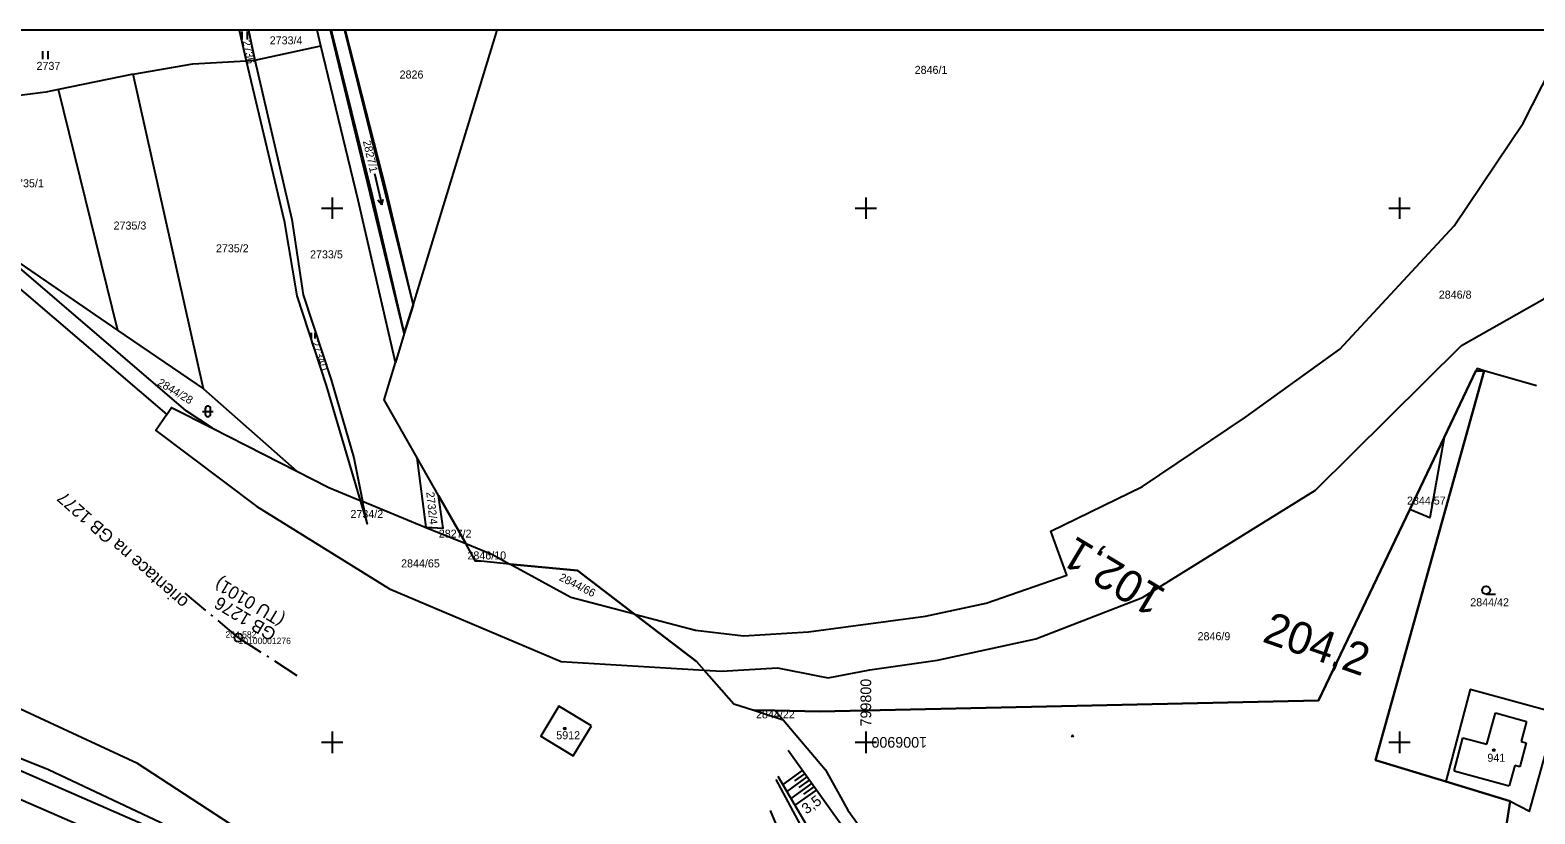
# Model space of a CAD drawing. Extents: x -800194 to -799078, y -1007177 to -1006597.
# Drawn here: x -799956.6 to -799674.6, y -1006913.4 to -1006766.6 of the extents above; entities that cross this region are included whole.
import ezdxf

# ---------------------------------------------------------------- set-up
doc = ezdxf.new("R2010")
doc.units = 0
for name, color, linetype in [('_Vrstva 7 - Přesunutá', 7, 'Continuous'), ('Dočasné zábory', 7, 'Continuous'), ('Legenda 1', 7, 'Continuous'), ('Ramove udaje', 7, 'Continuous'), ('Vrstva 48', 7, 'Continuous'), ('Vrstva 49', 7, 'Continuous'), ('Vrstva 53', 7, 'Continuous'), ('Vrstva 55', 7, 'Continuous'), ('Vrstva 56', 7, 'Continuous'), ('Vrstva 57', 7, 'Continuous'), ('Vrstva 58', 7, 'Continuous'), ('Vrstva 59', 7, 'Continuous'), ('Vrstva 60', 7, 'Continuous'), ('Vrstva 61', 7, 'Continuous'), ('Vrstva 63', 7, 'Continuous'), ('Vrstva 7', 7, 'Continuous')]:
    doc.layers.add(name, color=color, linetype=linetype)

msp = doc.modelspace()

# ---------------------------------------------------------------- linework, layer by layer
at = {"layer": 'Dočasné zábory'}
for points in [[(-799967.93, -1006901.13), (-799932.44, -1006916.61), (-799908.96, -1006929.95), (-799851.52, -1006962.6), (-799849.43, -1006965.58), (-799838.48, -1006981.29), (-799834.59, -1006980.15), (-799830.67, -1006986.18), (-799829.24, -1006997.61), (-799828.14, -1006999.18)], [(-799827.49, -1007007.33), (-799833.05, -1007000.26), (-799836.6, -1006993.51), (-799842.29, -1006982.66), (-799845.94, -1006977.53), (-799850.11, -1006971.65), (-799853.92, -1006967.55), (-799855.04, -1006966.34), (-799901.91, -1006939.71), (-799934.68, -1006921.09), (-799969.58, -1006905.87)]]:
    msp.add_lwpolyline(points, dxfattribs=at)
at = {"layer": 'Legenda 1'}
msp.add_lwpolyline([(-800193.4, -1007176.65), (-799312.4, -1007176.65), (-799312.4, -1006766.65), (-800193.4, -1006766.65)], close=True, dxfattribs=at)
at = {"layer": 'Ramove udaje'}
for p, q in [((-799900, -1006798), (-799900, -1006802)), ((-799800, -1006798), (-799800, -1006802)), ((-799700, -1006798), (-799700, -1006802)), ((-799902, -1006800), (-799900, -1006800)), ((-799900, -1006800), (-799898, -1006800)), ((-799802, -1006800), (-799800, -1006800)), ((-799800, -1006800), (-799798, -1006800)), ((-799702, -1006800), (-799700, -1006800)), ((-799700, -1006800), (-799698, -1006800)), ((-799900, -1006898), (-799900, -1006902)), ((-799800, -1006898), (-799800, -1006902)), ((-799700, -1006898), (-799700, -1006902)), ((-799902, -1006900), (-799900, -1006900)), ((-799900, -1006900), (-799898, -1006900)), ((-799802, -1006900), (-799800, -1006900)), ((-799800, -1006900), (-799798, -1006900)), ((-799702, -1006900), (-799700, -1006900)), ((-799700, -1006900), (-799698, -1006900))]:
    msp.add_line(p, q, dxfattribs=at)
at = {"layer": 'Vrstva 48'}
for p, q in [((-799811.93, -1006905.27), (-799815.58, -1006907.89)), ((-799811.05, -1006906.49), (-799814.82, -1006909.19)), ((-799811.49, -1006905.88), (-799813.35, -1006907.21)), ((-799810.18, -1006907.71), (-799814.06, -1006910.49)), ((-799809.31, -1006908.93), (-799813.3, -1006911.79)), ((-799810.62, -1006907.1), (-799812.53, -1006908.47)), ((-799809.74, -1006908.32), (-799811.71, -1006909.73))]:
    msp.add_line(p, q, dxfattribs=at)
at = {"layer": 'Vrstva 49'}
for p, q in [((-799761.44, -1006898.59), (-799761.08, -1006898.95)), ((-799761.44, -1006898.95), (-799761.08, -1006898.59))]:
    msp.add_line(p, q, dxfattribs=at)
for points in [[(-799779.16, -1006943.33), (-799796.9, -1006926.25), (-799814.58, -1006901.56)], [(-799816.48, -1006906.34), (-799809.08, -1006919.03), (-799804.33, -1006925.79)], [(-799804.93, -1006926.45), (-799809.53, -1006920.44), (-799816.79, -1006906.94)], [(-799817.93, -1006912.77), (-799815.19, -1006919.41), (-799811.75, -1006925.64), (-799808.12, -1006930.68), (-799809.62, -1006932.5), (-799809.74, -1006938.63), (-799809.9, -1006941.36)]]:
    msp.add_lwpolyline(points, dxfattribs=at)
at = {"layer": 'Vrstva 53'}
for points in [[(-799897.71, -1006766.65), (-799884.86, -1006818.16), (-799886.49, -1006823.47), (-799900.34, -1006766.65)], [(-799963.94, -1006806.68), (-799940.15, -1006822.89), (-799924.15, -1006833.79), (-799906.63, -1006849.24), (-799900.66, -1006852.28), (-799894.78, -1006854.69), (-799894.32, -1006854.87), (-799882.56, -1006859.69), (-799879.2, -1006859.87), (-799880.09, -1006853.81), (-799874.98, -1006862.8), (-799869.94, -1006864.86), (-799866.71, -1006866.63), (-799854.06, -1006867.84), (-799843.37, -1006876), (-799831.75, -1006884.86), (-799830.3, -1006886.5), (-799824.73, -1006892.78), (-799821.02, -1006893.98), (-799817.05, -1006894.06), (-799808.6, -1006894.22), (-799715.17, -1006892.15), (-799698.08, -1006856.38), (-799691.64, -1006842.91), (-799685.69, -1006830.46), (-799684.1, -1006830.47), (-799704.46, -1006903.31), (-799691.31, -1006907.33), (-799679.26, -1006911.01), (-799685.71, -1006952.41)], [(-799673.33, -1007118.14), (-799714.71, -1007110.97), (-799718.21, -1007083.69), (-799729.93, -1007087.54), (-799766.47, -1007095.84), (-799767.73, -1007094.8), (-799769.22, -1007093.56), (-799785.06, -1007080.42), (-799809.11, -1007056.81), (-799818.59, -1007034.4), (-799822.79, -1007029.13), (-799826.14, -1007024.13), (-799830.75, -1006966.73), (-799839.73, -1006961.33), (-799877.87, -1006942.17), (-799936.47, -1006903.99), (-799954.76, -1006895.45), (-799964.79, -1006890.84)]]:
    msp.add_lwpolyline(points, dxfattribs=at)
at = {"layer": 'Vrstva 55'}
for p, q in [((-799917.43, -1006766.65), (-799916.1, -1006772.38)), ((-799915.71, -1006766.65), (-799914.5, -1006772.29)), ((-799902.13, -1006769.59), (-799902.84, -1006766.65)), ((-799884.86, -1006818.16), (-799869.08, -1006766.65)), ((-799914.5, -1006772.29), (-799902.13, -1006769.59)), ((-799895.13, -1006798.48), (-799902.13, -1006769.59)), ((-799916.1, -1006772.38), (-799914.5, -1006772.29)), ((-799937.29, -1006774.9), (-799951.32, -1006777.78)), ((-799924.15, -1006833.79), (-799937.29, -1006774.9)), ((-799953.68, -1006778.26), (-799969.88, -1006780.37)), ((-799951.32, -1006777.78), (-799953.68, -1006778.26)), ((-799940.15, -1006822.89), (-799951.32, -1006777.78)), ((-799888.13, -1006828.86), (-799895.13, -1006798.48)), ((-799963.94, -1006806.68), (-799940.15, -1006822.89)), ((-799965.36, -1006809.25), (-799930.99, -1006838.59)), ((-799886.49, -1006823.47), (-799884.86, -1006818.16)), ((-799940.15, -1006822.89), (-799924.15, -1006833.79)), ((-799886.49, -1006823.47), (-799888.13, -1006828.86)), ((-799685.69, -1006830.46), (-799691.64, -1006842.91)), ((-799674.35, -1006833.26), (-799684.1, -1006830.47)), ((-799924.15, -1006833.79), (-799906.63, -1006849.24)), ((-799922.45, -1006841.18), (-799906.63, -1006849.24)), ((-799691.64, -1006842.91), (-799698.08, -1006856.38)), ((-799882.39, -1006859.7), (-799884.1, -1006846.76)), ((-799880.09, -1006853.81), (-799884.1, -1006846.76)), ((-799894.78, -1006854.69), (-799894.32, -1006854.87)), ((-799894.32, -1006854.87), (-799882.56, -1006859.69)), ((-799874.98, -1006862.8), (-799880.09, -1006853.81)), ((-799698.08, -1006856.38), (-799715.17, -1006892.15)), ((-799882.56, -1006859.69), (-799882.39, -1006859.7)), ((-799882.56, -1006859.69), (-799874.98, -1006862.8)), ((-799817.05, -1006894.06), (-799821.02, -1006893.98)), ((-799821.02, -1006893.98), (-799815.49, -1006895.78)), ((-799817.05, -1006894.06), (-799815.49, -1006895.78)), ((-799679.26, -1006911.01), (-799691.31, -1006907.33))]:
    msp.add_line(p, q, dxfattribs=at)
for points in [[(-799900.21, -1006766.65), (-799892.52, -1006797.61), (-799886.49, -1006823.47)], [(-799897.57, -1006766.65), (-799889.91, -1006796.74), (-799884.86, -1006818.16)], [(-799843.37, -1006876), (-799831.92, -1006878.98), (-799822.92, -1006880.05), (-799810.74, -1006879.32), (-799788.82, -1006876.36), (-799777.45, -1006873.96), (-799762.31, -1006868.73), (-799765.35, -1006860.47), (-799748.13, -1006852.13), (-799728.87, -1006839.09), (-799711.19, -1006826.38), (-799689.75, -1006803.29), (-799676.83, -1006784.06), (-799667.97, -1006766.65)], [(-799830.3, -1006886.5), (-799827.05, -1006886.7), (-799816.55, -1006886.06), (-799808.97, -1006887.52), (-799807.07, -1006887.91), (-799799.23, -1006886.45), (-799786.57, -1006884.64), (-799768.13, -1006880.63), (-799748.15, -1006872.9), (-799715.76, -1006852.76), (-799688.4, -1006825.67), (-799672.84, -1006816.93), (-799646.34, -1006766.65)], [(-799937.29, -1006774.9), (-799926.1, -1006772.97), (-799916.1, -1006772.38)], [(-799916.1, -1006772.38), (-799909.03, -1006802.36), (-799906.63, -1006816.4), (-799901.12, -1006833.19), (-799894.78, -1006854.69)], [(-799914.5, -1006772.29), (-799907.57, -1006802.13), (-799905.43, -1006816.22), (-799900.18, -1006832.12), (-799895.95, -1006846.75), (-799894.32, -1006854.87)], [(-799922.45, -1006841.18), (-799927.36, -1006837.92), (-799963.94, -1006806.68)], [(-799884.1, -1006846.76), (-799890.29, -1006835.89), (-799888.13, -1006828.86)], [(-799684.1, -1006830.47), (-799685.46, -1006829.98), (-799685.69, -1006830.46)], [(-799691.31, -1006907.33), (-799704.46, -1006903.31), (-799684.1, -1006830.47)], [(-799930.99, -1006838.59), (-799933.07, -1006841.6), (-799914.11, -1006855.86), (-799889.24, -1006871.28), (-799857.12, -1006884.86), (-799830.3, -1006886.5)], [(-799930.99, -1006838.59), (-799930.09, -1006837.28), (-799922.45, -1006841.18)], [(-799691.64, -1006842.91), (-799694.3, -1006857.94), (-799698.08, -1006856.38)], [(-799906.63, -1006849.24), (-799900.66, -1006852.28), (-799894.78, -1006854.69)], [(-799894.78, -1006854.69), (-799893.48, -1006859.09), (-799894.32, -1006854.87)], [(-799882.39, -1006859.7), (-799879.2, -1006859.87), (-799880.09, -1006853.81)], [(-799874.98, -1006862.8), (-799869.94, -1006864.86), (-799866.71, -1006866.63)], [(-799866.71, -1006866.63), (-799872.12, -1006866.11), (-799873.12, -1006866.06), (-799874.98, -1006862.8)], [(-799843.37, -1006876), (-799855.29, -1006872.89), (-799866.71, -1006866.63)], [(-799843.37, -1006876), (-799854.06, -1006867.84), (-799866.71, -1006866.63)], [(-799830.3, -1006886.5), (-799831.75, -1006884.86), (-799843.37, -1006876)], [(-799830.3, -1006886.5), (-799824.73, -1006892.78), (-799821.02, -1006893.98)], [(-799901.69, -1006974.63), (-799900.54, -1006973.82), (-799898.31, -1006947.43), (-799904.63, -1006933.89), (-799915, -1006924.46), (-799932.22, -1006915.03), (-799953.17, -1006905.18), (-799968.93, -1006898.86), (-799993.08, -1006892.39), (-800012.71, -1006890.11), (-800033.89, -1006890), (-800048.34, -1006892.35)], [(-799839.73, -1006961.33), (-799877.87, -1006942.17), (-799936.47, -1006903.99), (-799954.76, -1006895.45), (-799964.79, -1006890.84)], [(-799715.17, -1006892.15), (-799808.6, -1006894.22), (-799817.05, -1006894.06)], [(-799670.51, -1006894.51), (-799686.74, -1006890.11), (-799691.31, -1006907.33)], [(-799851.43, -1006896.91), (-799857.54, -1006893.23), (-799860.93, -1006898.86), (-799854.86, -1006902.52), (-799851.43, -1006896.91)], [(-799679.26, -1006911.01), (-799675.61, -1006912.91), (-799670.51, -1006894.51)], [(-799815.49, -1006895.78), (-799807.53, -1006905.17), (-799803.4, -1006912.69), (-799785.23, -1006937.71)], [(-799686.25, -1006963.73), (-799685.71, -1006952.41), (-799679.26, -1006911.01)]]:
    msp.add_lwpolyline(points, dxfattribs=at)
at = {"layer": 'Vrstva 56'}
for p, q in [((-799683.63, -1006900.36), (-799682.01, -1006894.5)), ((-799682.01, -1006894.5), (-799676.18, -1006896.08)), ((-799676.18, -1006896.08), (-799677.18, -1006899.82)), ((-799689.75, -1006905.35), (-799688.1, -1006899.14)), ((-799688.1, -1006899.14), (-799683.63, -1006900.36)), ((-799676.24, -1006900.07), (-799677.44, -1006904.58)), ((-799677.18, -1006899.82), (-799676.24, -1006900.07)), ((-799689.75, -1006905.35), (-799679.43, -1006908.15)), ((-799678.41, -1006904.32), (-799679.43, -1006908.15)), ((-799677.44, -1006904.58), (-799678.41, -1006904.32))]:
    msp.add_line(p, q, dxfattribs=at)
at = {"layer": 'Vrstva 58'}
for p, q in [((-799916.86, -1006768.43), (-799916.86, -1006766.93)), ((-799915.86, -1006768.43), (-799915.86, -1006766.93)), ((-799954.2, -1006772.07), (-799954.2, -1006770.57)), ((-799953.2, -1006772.07), (-799953.2, -1006770.57)), ((-799892.08, -1006793.51), (-799890.73, -1006799.35)), ((-799890.73, -1006799.35), (-799891.44, -1006798.51)), ((-799890.73, -1006799.35), (-799890.46, -1006798.29)), ((-799903.86, -1006824.36), (-799903.86, -1006823.35)), ((-799903.19, -1006824.36), (-799903.19, -1006823.35)), ((-799924.3, -1006838.04), (-799922.3, -1006838.04)), ((-799923.8, -1006837.54), (-799923.8, -1006838.54)), ((-799922.8, -1006838.54), (-799922.8, -1006837.54)), ((-799683.77, -1006872.27), (-799682.02, -1006872.27))]:
    msp.add_line(p, q, dxfattribs=at)
msp.add_circle((-799683.77, -1006871.52), 0.75, dxfattribs=at)
for centre, start, end in [((-799923.3, -1006837.54), 0, 180), ((-799923.3, -1006838.54), 180, 359.9879)]:
    msp.add_arc(centre, 0.5, start, end, dxfattribs=at)
at = {"layer": 'Vrstva 59'}
for centre in [(-799856.4, -1006897.43), (-799682.3, -1006901.44)]:
    msp.add_circle(centre, 0.175, dxfattribs=at)
at = {"layer": 'Vrstva 60'}
msp.add_line((-799917.56, -1006880.41), (-799917.56, -1006880.41), dxfattribs=at)
at = {"layer": 'Vrstva 63'}
for p, q in [((-799923.71, -1006875.3), (-799927.55, -1006872.1)), ((-799922.4, -1006876.38), (-799922.71, -1006876.13)), ((-799917.56, -1006880.41), (-799921.4, -1006877.21)), ((-799917.51, -1006880.44), (-799917.6, -1006880.38)), ((-799917.56, -1006880.41), (-799913.36, -1006883.13)), ((-799912.27, -1006883.83), (-799911.93, -1006884.05)), ((-799910.84, -1006884.76), (-799906.64, -1006887.47))]:
    msp.add_line(p, q, dxfattribs=at)
msp.add_circle((-799917.56, -1006880.41), 0.756, dxfattribs=at)

# ---------------------------------------------------------------- texts
at = {"layer": '_Vrstva 7 - Přesunutá'}
msp.add_text('204,2', height=6, rotation=340.8787, dxfattribs=at).set_placement((-799725.91, -1006881.09))
at = {"layer": 'Ramove udaje'}
for s, rotation, p in [('    799800', 90, (-799799, -1006900)), ('1006900    ', 180, (-799788.53, -1006899))]:
    msp.add_text(s, height=2, rotation=rotation, dxfattribs=at).set_placement(p)
at = {"layer": 'Vrstva 48'}
msp.add_text('3,5', height=2, rotation=35.6162, dxfattribs=at).set_placement((-799811.13, -1006913.54))
at = {"layer": 'Vrstva 57'}
for s, p in [('2733/4', (-799911.71, -1006769.31)), ('2737', (-799955.41, -1006774.09)), ('2846/1', (-799790.85, -1006774.84)), ('2826', (-799887.37, -1006775.71)), ('2735/1', (-799960.17, -1006796.07)), ('2735/3', (-799940.97, -1006803.99)), ('2735/2', (-799921.79, -1006808.25)), ('2733/5', (-799904.15, -1006809.39)), ('2846/8', (-799692.63, -1006816.92)), ('2844/57', (-799698.59, -1006855.49)), ('2734/2', (-799896.58, -1006858)), ('2827/2', (-799880.03, -1006861.68)), ('2846/10', (-799874.66, -1006865.76)), ('2844/65', (-799887.09, -1006867.25)), ('2844/42', (-799686.73, -1006874.52)), ('2846/9', (-799737.83, -1006880.88)), ('2844/22', (-799820.58, -1006895.51)), ('5912', (-799858.01, -1006899.42)), ('941', (-799683.52, -1006903.64))]:
    msp.add_text(s, height=1.5, dxfattribs=at).set_placement(p)
for s, rotation, p in [('2736', 282, (-799916.82, -1006768.71)), ('2827/1', 283, (-799894.26, -1006787.46)), ('2734/1', 289.2956, (-799904, -1006825.1)), ('2844/28', 329, (-799932.89, -1006833.03)), ('2732/4', 276, (-799882.37, -1006853.18)), ('2844/66', 333, (-799857.61, -1006869.57))]:
    msp.add_text(s, height=1.5, rotation=rotation, dxfattribs=at).set_placement(p)
at = {"layer": 'Vrstva 60'}
msp.add_text('10100001276', height=1.2, dxfattribs=at).set_placement((-799917.56, -1006881.61))
at = {"layer": 'Vrstva 61'}
msp.add_text('204.582', height=1.2, dxfattribs=at).set_placement((-799920, -1006880.41))
at = {"layer": 'Vrstva 63'}
for s, rotation, p in [('orientace na GB 1277', 138.6124, (-799926.77, -1006873.43)), ('(TU 0101)', 149.0426, (-799908.68, -1006876.43)), ('GB 1276', 149.0426, (-799910.27, -1006879.1))]:
    msp.add_text(s, height=2.4, rotation=rotation, dxfattribs=at).set_placement(p)
at = {"layer": 'Vrstva 7'}
msp.add_text('102,1', height=6, rotation=149.057, dxfattribs=at).set_placement((-799743.44, -1006871.61))

doc.saveas('drawing.dxf')
